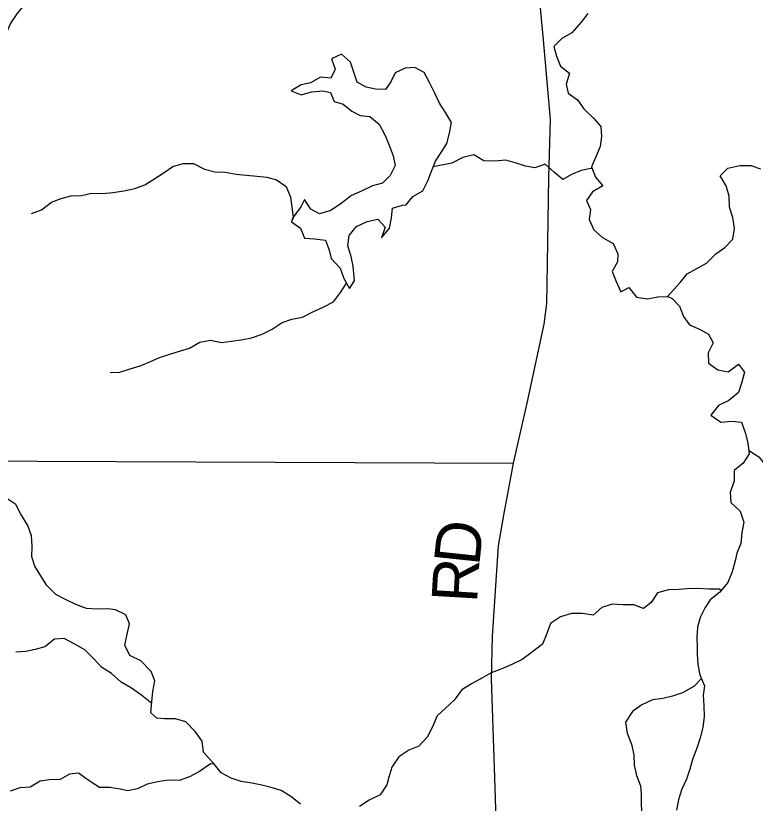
# Model space of a CAD drawing. Extents: x 1985906 to 2277390, y 930619 to 1324581.
# Drawn here: x 2156932 to 2161796, y 1124636 to 1129818 of the extents above; entities that cross this region are included whole.
import ezdxf

# ---------------------------------------------------------------- set-up
doc = ezdxf.new("R2010")
doc.units = 0
for name, color, linetype in [('GM_X_County_Road', 7, 'Continuous'), ('GM_X_County_Road_Text', 7, 'Continuous'), ('GM_X_Major_River', 7, 'Continuous'), ('GM_X_Minor_Lake', 7, 'Continuous'), ('GM_X_Minor_River', 7, 'Continuous'), ('GM_X_Township_Road', 7, 'Continuous')]:
    doc.layers.add(name, color=color, linetype=linetype)

msp = doc.modelspace()

# ---------------------------------------------------------------- linework, layer by layer
at = {"layer": 'GM_X_County_Road'}
for points in [[(2160206.6, 1126874.1), (2160296.2, 1127268.6), (2160407.7, 1127789.2), (2160425.6, 1127923.3), (2160429.3, 1128187.6), (2160438.9, 1128754.1), (2160448.5, 1129134.5), (2160404.1, 1129658.9), (2160351.7, 1130221.4), (2160309.5, 1130445.5), (2160247.4, 1130605.6), (2160175.3, 1130769.7), (2160007.1, 1131067.8), (2159688.8, 1131599.9), (2159287.3, 1132388.6)], [(2160099.3, 1119135), (2160113.4, 1123735.2), (2160107.1, 1124051.5), (2160080.4, 1124870.2), (2160061.9, 1125454.7), (2160067.7, 1125734.9), (2160107.1, 1126329.5), (2160142.9, 1126531.7), (2160206.6, 1126874.1)]]:
    msp.add_lwpolyline(points, dxfattribs=at)
at = {"layer": 'GM_X_Major_River'}
for points in [[(2160694.6, 1129832.8), (2160650.9, 1129774.6), (2160589.2, 1129704.2), (2160523.4, 1129667.9), (2160471.6, 1129615.6), (2160489.8, 1129551.6), (2160516.1, 1129485.7), (2160574.3, 1129439.9), (2160552.6, 1129367.7), (2160564.8, 1129307.7), (2160627, 1129263.9), (2160669.2, 1129204.1), (2160731.4, 1129144.3), (2160779.6, 1129088.4), (2160785.9, 1129022.4), (2160776.2, 1128956.3), (2160748.5, 1128890.1), (2160718.7, 1128823.9), (2160745, 1128755.9), (2160793.2, 1128698.1), (2160725.4, 1128659.8), (2160685.7, 1128601.5), (2160711.9, 1128541.6), (2160704.2, 1128477.5), (2160734.4, 1128409.5), (2160790.6, 1128357.7), (2160860.8, 1128320), (2160893, 1128250.1), (2160889.2, 1128198), (2160855.5, 1128133.8), (2160881.8, 1128067.8)], [(2160881.8, 1128067.8), (2160912, 1128001.9), (2160963.9, 1128030.2), (2161016.1, 1127966.3), (2161088.2, 1127954.6), (2161156.1, 1127968.9), (2161220, 1127969.2)]]:
    msp.add_lwpolyline(points, dxfattribs=at)
at = {"layer": 'GM_X_Minor_Lake'}
for points in [[(2159476.3, 1128572.2), (2159500.3, 1128572.3), (2159544, 1128628.6), (2159609.9, 1128664.9), (2159643.6, 1128731.1), (2159667.3, 1128795.2), (2159693, 1128861.4), (2159726.8, 1128911.6), (2159768.5, 1128975.9), (2159784.2, 1129044), (2159797.9, 1129116.1), (2159757.7, 1129182), (2159719.4, 1129241.9), (2159687.2, 1129311.9), (2159652.9, 1129377.8), (2159618.7, 1129443.7), (2159556.5, 1129477.5), (2159492.6, 1129473.2), (2159428.7, 1129442.9), (2159399, 1129382.7), (2159363.2, 1129332.5), (2159299.2, 1129334.2), (2159237.2, 1129347.9), (2159177.1, 1129379.7), (2159154.8, 1129445.7), (2159134.6, 1129511.6), (2159074.4, 1129565.4), (2159008.5, 1129533.1), (2159032.8, 1129465.1), (2159005.1, 1129407), (2158937.1, 1129412.7), (2158871.2, 1129376.3), (2158809.3, 1129362.1), (2158743.5, 1129323.7), (2158809.6, 1129298), (2158877.5, 1129316.3), (2158951.4, 1129324.6), (2159001.5, 1129312.8), (2159025.7, 1129252.9), (2159085.7, 1129235.1), (2159141.9, 1129189.3), (2159198, 1129161.6), (2159262, 1129153.8), (2159322.2, 1129104.1), (2159360.5, 1129034.1), (2159388.7, 1128966.2), (2159415, 1128896.2), (2159427.3, 1128832.2), (2159395.5, 1128766), (2159343.8, 1128715.8), (2159277.9, 1128697.4), (2159210, 1128665.1), (2159140.2, 1128634.8), (2159072.4, 1128582.4), (2159004.6, 1128536.1), (2158930.8, 1128513.7), (2158872.7, 1128545.5), (2158832.4, 1128609.4), (2158806.6, 1128559.2), (2158757.9, 1128494.1)], [(2159476.3, 1128572.2), (2159500.3, 1128572.3), (2159544, 1128628.6), (2159609.9, 1128664.9), (2159643.6, 1128731.1), (2159667.3, 1128795.2), (2159693, 1128861.4), (2159726.8, 1128911.6), (2159768.5, 1128975.9), (2159784.2, 1129044), (2159797.9, 1129116.1), (2159757.7, 1129182), (2159719.4, 1129241.9), (2159687.2, 1129311.9), (2159652.9, 1129377.8), (2159618.7, 1129443.7), (2159556.5, 1129477.5), (2159492.6, 1129473.2), (2159428.7, 1129442.9), (2159399, 1129382.7), (2159363.2, 1129332.5), (2159299.2, 1129334.2), (2159237.2, 1129347.9), (2159177.1, 1129379.7), (2159154.8, 1129445.7), (2159134.6, 1129511.6), (2159074.4, 1129565.4), (2159008.5, 1129533.1), (2159032.8, 1129465.1), (2159005.1, 1129407), (2158937.1, 1129412.7), (2158871.2, 1129376.3), (2158809.3, 1129362.1), (2158743.5, 1129323.7), (2158809.6, 1129298), (2158877.5, 1129316.3), (2158951.4, 1129324.6), (2159001.5, 1129312.8), (2159025.7, 1129252.9), (2159085.7, 1129235.1), (2159141.9, 1129189.3), (2159198, 1129161.6), (2159262, 1129153.8), (2159322.2, 1129104.1), (2159360.5, 1129034.1), (2159388.7, 1128966.2), (2159415, 1128896.2), (2159427.3, 1128832.2), (2159395.5, 1128766), (2159343.8, 1128715.8), (2159277.9, 1128697.4), (2159210, 1128665.1), (2159140.2, 1128634.8), (2159072.4, 1128582.4), (2159004.6, 1128536.1), (2158930.8, 1128513.7), (2158872.7, 1128545.5), (2158832.4, 1128609.4), (2158806.6, 1128559.2), (2158757.4, 1128493.3)], [(2158757.9, 1128494.1), (2158745.1, 1128460.9), (2158805.2, 1128419.1), (2158831.5, 1128355.1), (2158897.5, 1128349.4), (2158969.5, 1128341.7), (2158993.7, 1128275.8), (2159005.9, 1128219.8), (2159066.2, 1128156), (2159090.5, 1128088), (2159126.7, 1128022.1), (2159160.5, 1128074.3), (2159152.1, 1128170.4), (2159137.8, 1128234.4), (2159115.6, 1128304.3), (2159125.3, 1128372.4), (2159173, 1128430.7), (2159242.8, 1128463.1), (2159314.7, 1128479.4), (2159360.9, 1128427.5), (2159337.2, 1128355.4), (2159391, 1128419.7), (2159402.7, 1128487.8), (2159410.4, 1128551.9), (2159476.3, 1128572.2)], [(2158757.6, 1128493.4), (2158745.1, 1128460.9), (2158805.2, 1128419.1), (2158831.5, 1128355.1), (2158897.5, 1128349.4), (2158969.5, 1128341.7), (2158993.7, 1128275.8), (2159005.9, 1128219.8), (2159066.2, 1128156), (2159090.5, 1128088), (2159126.7, 1128022.1), (2159160.5, 1128074.3), (2159152.1, 1128170.4), (2159137.8, 1128234.4), (2159115.6, 1128304.3), (2159125.3, 1128372.4), (2159173, 1128430.7), (2159242.8, 1128463.1), (2159314.7, 1128479.4), (2159360.9, 1128427.5), (2159337.2, 1128355.4), (2159391, 1128419.7), (2159402.7, 1128487.8), (2159410.4, 1128551.9), (2159476.3, 1128572.2)]]:
    msp.add_lwpolyline(points, dxfattribs=at)
at = {"layer": 'GM_X_Minor_River'}
for points in [[(2156281.9, 1128998.6), (2156345.6, 1129066.9), (2156395.3, 1129135.2), (2156461, 1129197.6), (2156516.7, 1129261.8), (2156554.4, 1129326.1), (2156594.1, 1129390.3), (2156647.9, 1129448.6), (2156713.6, 1129509), (2156757.3, 1129571.2), (2156813, 1129637.5), (2156868.8, 1129699.8), (2156898.5, 1129764), (2156942.2, 1129830.3), (2156991.9, 1129890.6), (2157061.7, 1129925)], [(2160722.3, 1128814.7), (2160714.8, 1128811.8), (2160650.9, 1128799.6), (2160587, 1128773.3), (2160531.2, 1128741), (2160475, 1128786.8), (2160414.8, 1128840.6), (2160346.9, 1128816.2), (2160284.9, 1128828), (2160216.8, 1128849.7), (2160154.8, 1128867.5), (2160082.9, 1128861.1), (2160010.9, 1128862.8), (2159944.7, 1128902.6), (2159872.8, 1128884.2), (2159801, 1128847.9), (2159678.3, 1128823.6)], [(2157035.6, 1128515.4), (2157101.4, 1128539.7), (2157167.2, 1128590.1), (2157231.1, 1128614.4), (2157295, 1128632.7), (2157364.9, 1128635), (2157430.8, 1128649.3), (2157502.8, 1128647.6), (2157570.8, 1128653.9), (2157642.7, 1128666.2), (2157714.6, 1128680.6), (2157780.5, 1128704.9), (2157840.3, 1128743.2), (2157902.1, 1128781.5), (2157965.9, 1128825.8), (2158033.8, 1128846.1), (2158101.8, 1128846.4), (2158173.9, 1128808.7), (2158241.9, 1128791), (2158309.9, 1128787.3), (2158381.9, 1128775.6), (2158449.9, 1128767.9), (2158517.9, 1128762.2), (2158583.9, 1128756.5), (2158648, 1128738.7), (2158710.1, 1128694.9), (2158738.4, 1128623), (2158757.4, 1128493.3)], [(2161219.7, 1127969.2), (2161301.6, 1128061.6), (2161349.4, 1128119.9), (2161411.2, 1128154.2), (2161475, 1128188.5), (2161536.7, 1128250.9), (2161596.6, 1128293.2), (2161648.3, 1128347.4), (2161660, 1128417.6), (2161647.7, 1128489.6), (2161627.4, 1128557.6), (2161625.2, 1128629.6), (2161604.9, 1128697.6), (2161564.6, 1128763.5), (2161616.4, 1128813.8), (2161694.3, 1128832.1), (2161766.3, 1128832.4), (2161830.3, 1128810.7)], [(2157553.6, 1127470.7), (2157617.6, 1127472.9), (2157685.5, 1127493.2), (2157749.4, 1127513.6), (2157813.2, 1127539.9), (2157877.1, 1127568.2), (2157945, 1127590.5), (2158008.9, 1127610.8), (2158074.8, 1127631.1), (2158142.6, 1127669.4), (2158212.5, 1127681.8), (2158284.5, 1127668.1), (2158350.5, 1127676.4), (2158414.4, 1127684.6), (2158482.3, 1127699), (2158552.2, 1127723.3), (2158618, 1127755.6), (2158683.8, 1127799.9), (2158747.7, 1127820.2), (2158817.6, 1127834.6), (2158885.4, 1127868.9), (2158953.3, 1127899.2), (2159021.1, 1127935.6), (2159068.8, 1127995.8), (2159107.2, 1128057.6)], [(2161220.2, 1127969.5), (2161248.8, 1127956.4), (2161298.3, 1127905.5), (2161324.5, 1127839.5), (2161364.7, 1127783.6), (2161428.8, 1127755.9), (2161488.9, 1127722.1), (2161519.2, 1127664.2), (2161485.4, 1127600), (2161489.7, 1127531.9), (2161549.9, 1127488.2), (2161617.9, 1127474.4), (2161685.7, 1127524.8), (2161725.9, 1127472.9), (2161708.1, 1127406.8), (2161686.4, 1127338.6), (2161622.7, 1127286.3), (2161554.8, 1127253.9), (2161505.1, 1127189.7), (2161569.3, 1127143.9), (2161641.2, 1127150.2), (2161705.2, 1127142.5), (2161729.5, 1127074.5), (2161747.8, 1127006.5), (2161756.1, 1126934.5), (2161716.3, 1126874.3), (2161658.5, 1126826), (2161656.8, 1126753.9), (2161631.2, 1126681.7), (2161635.4, 1126613.7), (2161697.6, 1126557.9), (2161721.9, 1126485.9), (2161708.2, 1126417.8), (2161700.5, 1126345.7), (2161674.8, 1126281.5), (2161665, 1126231.4), (2161645.3, 1126159.3), (2161615.6, 1126087.1), (2161563.9, 1126024.8), (2161500.1, 1125974.4), (2161466.3, 1125924.2), (2161434.6, 1125858.1), (2161416.9, 1125793.9), (2161411.2, 1125725.8), (2161413.4, 1125665.8), (2161413.6, 1125615.7), (2161417.9, 1125547.7), (2161432.2, 1125479.7), (2161462.5, 1125407.7), (2161452.7, 1125347.6), (2161457, 1125277.6), (2161459.3, 1125205.5), (2161451.6, 1125133.4), (2161433.9, 1125065.3), (2161412.2, 1124997.1), (2161384.5, 1124922.9), (2161364.8, 1124858.8), (2161343, 1124794.6), (2161311.3, 1124724.4), (2161291.6, 1124658.3), (2161277.9, 1124590.1)], [(2161753.8, 1126954.3), (2161758, 1126954.5), (2161820.1, 1126914.8), (2161868.4, 1126852.9), (2161910.6, 1126787), (2161956.8, 1126731.2), (2161959.1, 1126665.1), (2161991.3, 1126599.2), (2162059.4, 1126577.5)], [(2158229.9, 1124901.2), (2158224.3, 1124907.8), (2158167.8, 1124971.6), (2158157.3, 1125043.6), (2158112.8, 1125107.4), (2158050.3, 1125171.1), (2157982.1, 1125190.7), (2157910, 1125190.2), (2157859.9, 1125195.9), (2157821.6, 1125229.7), (2157827.1, 1125303.8), (2157834.7, 1125370), (2157846.2, 1125440.2), (2157821.8, 1125502.1), (2157755.3, 1125571.8), (2157682.9, 1125607.4), (2157650.4, 1125675.3), (2157664, 1125747.5), (2157679.5, 1125815.7), (2157657.1, 1125875.7), (2157588.8, 1125909.2), (2157536.7, 1125914.9), (2157464.6, 1125912.4), (2157398.5, 1125918), (2157328.2, 1125943.5), (2157264, 1125973.2), (2157195.6, 1126008.8), (2157137.2, 1126068.5), (2157096.7, 1126132.3), (2157058.2, 1126196.2), (2157037.8, 1126258.1), (2157039.3, 1126326.2), (2157034.9, 1126396.3), (2157012.4, 1126464.3), (2156965.8, 1126538.1), (2156933.4, 1126602), (2156867, 1126645.6)], [(2161572.9, 1126035.6), (2161561.8, 1126044.8), (2161489.8, 1126044.5), (2161417.9, 1126048.2), (2161345.9, 1126045.8), (2161293.9, 1126041.6), (2161226, 1126039.3), (2161154.1, 1126021), (2161112.4, 1125956.8), (2161060.5, 1125916.5), (2160998.5, 1125942.2), (2160926.5, 1125941.9), (2160854.5, 1125945.6), (2160786.6, 1125923.3), (2160730.9, 1125873), (2160658.8, 1125884.7), (2160586.9, 1125884.4), (2160515, 1125862.1), (2160449.2, 1125817.7), (2160425.5, 1125753.6), (2160395.8, 1125683.4), (2160330, 1125631), (2160262.3, 1125580.7), (2160194.4, 1125548.4), (2160128.6, 1125520.1), (2160058.7, 1125493.7), (2159996.9, 1125459.4), (2159929.1, 1125421.1), (2159865.2, 1125382.8), (2159815.5, 1125314.5), (2159759.8, 1125260.2), (2159704, 1125209.9), (2159674.3, 1125137.7), (2159638.6, 1125069.5), (2159582.9, 1125011.2), (2159517, 1124984.9), (2159451.2, 1124940.5), (2159405.6, 1124872.3), (2159385.8, 1124806.1), (2159372, 1124756), (2159328.3, 1124689.8), (2159256.5, 1124655.4), (2159192.7, 1124615.1)], [(2157826.4, 1125294), (2157817.2, 1125299.8), (2157760.8, 1125345.4), (2157694.4, 1125393.1), (2157626, 1125432.7), (2157561.6, 1125490.3), (2157497.2, 1125530), (2157446.8, 1125583.7), (2157386.3, 1125645.4), (2157320, 1125683), (2157251.6, 1125718.6), (2157187.6, 1125714.2), (2157123.8, 1125665.7), (2157059.9, 1125647.2), (2156997.9, 1125634.8), (2156931.8, 1125630.3)], [(2161441.8, 1125456.7), (2161392.5, 1125403.4), (2161318.7, 1125363.1), (2161250.8, 1125340.8), (2161188.9, 1125324.5), (2161121, 1125316.2), (2161049.2, 1125283.8), (2160989.4, 1125239.5), (2160943.7, 1125169.2), (2160954, 1125097.2), (2160982.2, 1125025.3), (2160998.5, 1124953.3), (2161000.8, 1124887.2), (2161015.1, 1124817.2), (2161041.4, 1124749.3), (2161045.6, 1124699.2), (2161045.9, 1124627.2), (2161050.2, 1124555.1), (2161052.5, 1124483.1), (2161054.7, 1124413), (2161043, 1124348.9), (2161039.3, 1124276.8), (2161047.6, 1124208.8)], [(2158237.1, 1124892.2), (2158212.3, 1124895.7), (2158140.6, 1124845.2), (2158074.7, 1124808.6), (2158006.8, 1124786.1), (2157934.7, 1124787.7), (2157866.7, 1124777.2), (2157796.7, 1124760.7), (2157732.8, 1124730.2), (2157668.8, 1124717.8), (2157618.7, 1124727.4), (2157550.5, 1124739), (2157482.5, 1124738.5), (2157414.1, 1124782.1), (2157345.7, 1124833.8), (2157285.6, 1124827.3), (2157223.8, 1124790.9), (2157153.7, 1124790.4), (2157093.7, 1124780), (2157027.9, 1124741.5), (2156959.8, 1124737), (2156895.9, 1124714.5)], [(2158804.8, 1124629.4), (2158740.6, 1124679.2), (2158678.5, 1124718.9), (2158612.4, 1124738.7), (2158550.4, 1124754.4), (2158484.4, 1124768.1), (2158414.4, 1124777.8), (2158348.3, 1124799.6), (2158282.2, 1124835.3), (2158229.9, 1124901.2)]]:
    msp.add_lwpolyline(points, dxfattribs=at)
at = {"layer": 'GM_X_Township_Road'}
msp.add_lwpolyline([(2154459, 1126897.2), (2160206.6, 1126874.1)], dxfattribs=at)

# ---------------------------------------------------------------- texts
at = {"layer": 'GM_X_County_Road_Text'}
for s, rotation, p in [('D', 83.9635, (2159980.1, 1126192.5)), ('R', 86.626, (2159965.9, 1125950.2))]:
    msp.add_text(s, height=300, rotation=rotation, dxfattribs=at).set_placement(p)

doc.saveas('drawing.dxf')
